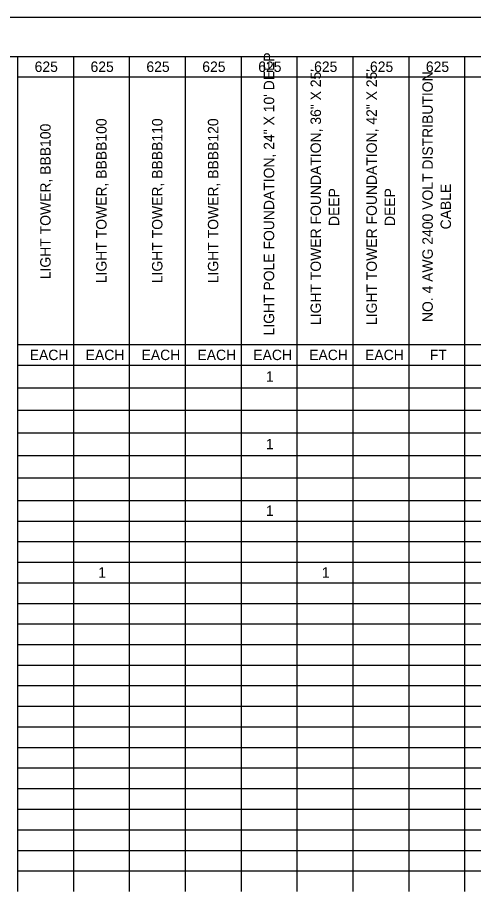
# Model space of a CAD drawing. Extents: x 0 to 34, y 0 to 22.
# Drawn here: x 12.63 to 18.49, y 10.78 to 22 of the extents above; entities that cross this region are included whole.
import ezdxf

# ---------------------------------------------------------------- set-up
doc = ezdxf.new("R2010")
doc.units = 0
for name, color, linetype in [('Default', 7, 'Continuous'), ('SH_Border', 7, 'Continuous'), ('SH_Cut_Line', 7, 'Continuous')]:
    doc.layers.add(name, color=color, linetype=linetype)

msp = doc.modelspace()

# ---------------------------------------------------------------- linework, layer by layer
at = {"layer": 'Default'}
for p, q in [((12.635, 21.5), (13.352, 21.5)), ((12.635, 21.5), (12.635, 21.236)), ((13.352, 21.5), (14.069, 21.5)), ((13.352, 21.5), (13.352, 21.236)), ((14.069, 21.5), (15.504, 21.5)), ((14.069, 21.5), (14.069, 21.236)), ((14.786, 21.5), (14.786, 21.236)), ((15.504, 21.5), (21.958, 21.5)), ((15.504, 21.5), (15.504, 21.236)), ((16.221, 21.5), (16.221, 21.236)), ((16.938, 21.5), (16.938, 21.236)), ((17.655, 21.5), (17.655, 21.236)), ((18.372, 21.5), (18.372, 21.236)), ((12.635, 21.236), (13.352, 21.236)), ((12.635, 21.236), (12.635, 20.972)), ((13.352, 21.236), (14.069, 21.236)), ((13.352, 21.236), (13.352, 20.972)), ((14.069, 21.236), (15.504, 21.236)), ((14.069, 21.236), (14.069, 20.972)), ((14.786, 21.236), (14.786, 20.972)), ((15.504, 21.236), (21.958, 21.236)), ((15.504, 21.236), (15.504, 20.972)), ((16.221, 21.236), (16.221, 20.972)), ((16.938, 21.236), (16.938, 20.972)), ((17.655, 21.236), (17.655, 20.972)), ((18.372, 21.236), (18.372, 20.972)), ((12.635, 20.972), (12.635, 20.707)), ((13.352, 20.972), (13.352, 20.707)), ((14.069, 20.972), (14.069, 20.707)), ((14.786, 20.972), (14.786, 20.707)), ((15.504, 20.972), (15.504, 20.707)), ((16.221, 20.972), (16.221, 20.707)), ((16.938, 20.972), (16.938, 20.707)), ((17.655, 20.972), (17.655, 20.707)), ((18.372, 20.972), (18.372, 20.707)), ((12.635, 20.707), (12.635, 20.443)), ((13.352, 20.707), (13.352, 20.443)), ((14.069, 20.707), (14.069, 20.443)), ((14.786, 20.707), (14.786, 20.443)), ((15.504, 20.707), (15.504, 20.443)), ((16.221, 20.707), (16.221, 20.443)), ((16.938, 20.707), (16.938, 20.443)), ((17.655, 20.707), (17.655, 20.443)), ((18.372, 20.707), (18.372, 20.443)), ((12.635, 20.443), (12.635, 20.179)), ((13.352, 20.443), (13.352, 20.179)), ((14.069, 20.443), (14.069, 20.179)), ((14.786, 20.443), (14.786, 20.179)), ((15.504, 20.443), (15.504, 20.179)), ((16.221, 20.443), (16.221, 20.179)), ((16.938, 20.443), (16.938, 20.179)), ((17.655, 20.443), (17.655, 20.179)), ((18.372, 20.443), (18.372, 20.179)), ((12.635, 20.179), (12.635, 19.915)), ((13.352, 20.179), (13.352, 19.915)), ((14.069, 20.179), (14.069, 19.915)), ((14.786, 20.179), (14.786, 19.915)), ((15.504, 20.179), (15.504, 19.915)), ((16.221, 20.179), (16.221, 19.915)), ((16.938, 20.179), (16.938, 19.915)), ((17.655, 20.179), (17.655, 19.915)), ((18.372, 20.179), (18.372, 19.915)), ((12.635, 19.915), (12.635, 19.651)), ((13.352, 19.915), (13.352, 19.651)), ((14.069, 19.915), (14.069, 19.651)), ((14.786, 19.915), (14.786, 19.651)), ((15.504, 19.915), (15.504, 19.651)), ((16.221, 19.915), (16.221, 19.651)), ((16.938, 19.915), (16.938, 19.651)), ((17.655, 19.915), (17.655, 19.651)), ((18.372, 19.915), (18.372, 19.651)), ((12.635, 19.651), (12.635, 19.122)), ((13.352, 19.651), (13.352, 19.122)), ((14.069, 19.651), (14.069, 19.122)), ((14.786, 19.651), (14.786, 19.122)), ((15.504, 19.651), (15.504, 19.122)), ((16.221, 19.651), (16.221, 19.122)), ((16.938, 19.651), (16.938, 19.122)), ((17.655, 19.651), (17.655, 19.122)), ((18.372, 19.651), (18.372, 19.122)), ((12.635, 19.122), (12.635, 18.329)), ((13.352, 19.122), (13.352, 18.329)), ((14.069, 19.122), (14.069, 18.329)), ((14.786, 19.122), (14.786, 18.329)), ((15.504, 19.122), (15.504, 18.329)), ((16.221, 19.122), (16.221, 18.329)), ((16.938, 19.122), (16.938, 18.329)), ((17.655, 19.122), (17.655, 18.329)), ((18.372, 19.122), (18.372, 18.329)), ((12.635, 18.329), (12.635, 18.065)), ((13.352, 18.329), (13.352, 18.065)), ((14.069, 18.329), (14.069, 18.065)), ((14.786, 18.329), (14.786, 18.065)), ((15.504, 18.329), (15.504, 18.065)), ((16.221, 18.329), (16.221, 18.065)), ((16.938, 18.329), (16.938, 18.065)), ((17.655, 18.329), (17.655, 18.065)), ((18.372, 18.329), (18.372, 18.065)), ((12.635, 18.065), (12.635, 17.537)), ((13.352, 18.065), (13.352, 17.537)), ((14.069, 18.065), (14.069, 17.537)), ((14.786, 18.065), (14.786, 17.537)), ((15.504, 18.065), (15.504, 17.537)), ((16.221, 18.065), (16.221, 17.537)), ((16.938, 18.065), (16.938, 17.537)), ((17.655, 18.065), (17.655, 17.537)), ((18.372, 18.065), (18.372, 17.537)), ((12.635, 17.801), (13.352, 17.801)), ((13.352, 17.801), (14.069, 17.801)), ((14.069, 17.801), (15.504, 17.801)), ((15.504, 17.801), (21.958, 17.801)), ((12.635, 17.537), (13.352, 17.537)), ((12.635, 17.537), (12.635, 17.247)), ((13.352, 17.537), (14.069, 17.537)), ((13.352, 17.537), (13.352, 17.247)), ((14.069, 17.537), (15.504, 17.537)), ((14.069, 17.537), (14.069, 17.247)), ((14.786, 17.537), (14.786, 17.247)), ((15.504, 17.537), (21.958, 17.537)), ((15.504, 17.537), (15.504, 17.247)), ((16.221, 17.537), (16.221, 17.247)), ((16.938, 17.537), (16.938, 17.247)), ((17.655, 17.537), (17.655, 17.247)), ((18.372, 17.537), (18.372, 17.247)), ((12.635, 17.247), (13.352, 17.247)), ((12.635, 17.247), (12.635, 15.801)), ((13.352, 17.247), (14.069, 17.247)), ((13.352, 17.247), (13.352, 15.801)), ((14.069, 17.247), (15.504, 17.247)), ((14.069, 17.247), (14.069, 15.801)), ((14.786, 17.247), (14.786, 15.801)), ((15.504, 17.247), (21.958, 17.247)), ((15.504, 17.247), (15.504, 15.801)), ((16.221, 17.247), (16.221, 15.801)), ((16.938, 17.247), (16.938, 15.801)), ((17.655, 17.247), (17.655, 15.801)), ((18.372, 17.247), (18.372, 15.801)), ((12.635, 16.958), (13.352, 16.958)), ((13.352, 16.958), (14.069, 16.958)), ((14.069, 16.958), (15.504, 16.958)), ((15.504, 16.958), (21.958, 16.958)), ((12.635, 16.669), (13.352, 16.669)), ((13.352, 16.669), (14.069, 16.669)), ((14.069, 16.669), (15.504, 16.669)), ((15.504, 16.669), (21.958, 16.669)), ((12.635, 16.379), (13.352, 16.379)), ((13.352, 16.379), (14.069, 16.379)), ((14.069, 16.379), (15.504, 16.379)), ((15.504, 16.379), (21.958, 16.379)), ((12.635, 16.09), (13.352, 16.09)), ((13.352, 16.09), (14.069, 16.09)), ((14.069, 16.09), (15.504, 16.09)), ((15.504, 16.09), (21.958, 16.09)), ((12.635, 15.801), (13.352, 15.801)), ((12.635, 15.801), (12.635, 15.272)), ((13.352, 15.801), (14.069, 15.801)), ((13.352, 15.801), (13.352, 15.272)), ((14.069, 15.801), (15.504, 15.801)), ((14.069, 15.801), (14.069, 15.272)), ((14.786, 15.801), (14.786, 15.272)), ((15.504, 15.801), (21.958, 15.801)), ((15.504, 15.801), (15.504, 15.272)), ((16.221, 15.801), (16.221, 15.272)), ((16.938, 15.801), (16.938, 15.272)), ((17.655, 15.801), (17.655, 15.272)), ((18.372, 15.801), (18.372, 15.272)), ((12.635, 15.536), (13.352, 15.536)), ((13.352, 15.536), (14.069, 15.536)), ((14.069, 15.536), (15.504, 15.536)), ((15.504, 15.536), (21.958, 15.536)), ((12.635, 15.272), (13.352, 15.272)), ((12.635, 15.272), (12.635, 15.008)), ((13.352, 15.272), (14.069, 15.272)), ((13.352, 15.272), (13.352, 15.008)), ((14.069, 15.272), (15.504, 15.272)), ((14.069, 15.272), (14.069, 15.008)), ((14.786, 15.272), (14.786, 15.008)), ((15.504, 15.272), (21.958, 15.272)), ((15.504, 15.272), (15.504, 15.008)), ((16.221, 15.272), (16.221, 15.008)), ((16.938, 15.272), (16.938, 15.008)), ((17.655, 15.272), (17.655, 15.008)), ((18.372, 15.272), (18.372, 15.008)), ((12.635, 15.008), (13.352, 15.008)), ((12.635, 15.008), (12.635, 14.479)), ((13.352, 15.008), (14.069, 15.008)), ((13.352, 15.008), (13.352, 14.479)), ((14.069, 15.008), (15.504, 15.008)), ((14.069, 15.008), (14.069, 14.479)), ((14.786, 15.008), (14.786, 14.479)), ((15.504, 15.008), (21.958, 15.008)), ((15.504, 15.008), (15.504, 14.479)), ((16.221, 15.008), (16.221, 14.479)), ((16.938, 15.008), (16.938, 14.479)), ((17.655, 15.008), (17.655, 14.479)), ((18.372, 15.008), (18.372, 14.479)), ((12.635, 14.744), (13.352, 14.744)), ((13.352, 14.744), (14.069, 14.744)), ((14.069, 14.744), (15.504, 14.744)), ((15.504, 14.744), (21.958, 14.744)), ((12.635, 14.479), (13.352, 14.479)), ((12.635, 14.479), (12.635, 13.423)), ((13.352, 14.479), (14.069, 14.479)), ((13.352, 14.479), (13.352, 13.423)), ((14.069, 14.479), (15.504, 14.479)), ((14.069, 14.479), (14.069, 13.423)), ((14.786, 14.479), (14.786, 13.423)), ((15.504, 14.479), (21.958, 14.479)), ((15.504, 14.479), (15.504, 13.423)), ((16.221, 14.479), (16.221, 13.423)), ((16.938, 14.479), (16.938, 13.423)), ((17.655, 14.479), (17.655, 13.423)), ((18.372, 14.479), (18.372, 13.423)), ((12.635, 14.215), (13.352, 14.215)), ((13.352, 14.215), (14.069, 14.215)), ((14.069, 14.215), (15.504, 14.215)), ((15.504, 14.215), (21.958, 14.215)), ((12.635, 13.951), (13.352, 13.951)), ((13.352, 13.951), (14.069, 13.951)), ((14.069, 13.951), (15.504, 13.951)), ((15.504, 13.951), (21.958, 13.951)), ((12.635, 13.687), (13.352, 13.687)), ((13.352, 13.687), (14.069, 13.687)), ((14.069, 13.687), (15.504, 13.687)), ((15.504, 13.687), (21.958, 13.687)), ((12.635, 13.423), (13.352, 13.423)), ((12.635, 13.423), (12.635, 13.158)), ((13.352, 13.423), (14.069, 13.423)), ((13.352, 13.423), (13.352, 13.158)), ((14.069, 13.423), (15.504, 13.423)), ((14.069, 13.423), (14.069, 13.158)), ((14.786, 13.423), (14.786, 13.158)), ((15.504, 13.423), (21.958, 13.423)), ((15.504, 13.423), (15.504, 13.158)), ((16.221, 13.423), (16.221, 13.158)), ((16.938, 13.423), (16.938, 13.158)), ((17.655, 13.423), (17.655, 13.158)), ((18.372, 13.423), (18.372, 13.158)), ((12.635, 13.158), (13.352, 13.158)), ((12.635, 13.158), (12.635, 12.894)), ((13.352, 13.158), (14.069, 13.158)), ((13.352, 13.158), (13.352, 12.894)), ((14.069, 13.158), (15.504, 13.158)), ((14.069, 13.158), (14.069, 12.894)), ((14.786, 13.158), (14.786, 12.894)), ((15.504, 13.158), (21.958, 13.158)), ((15.504, 13.158), (15.504, 12.894)), ((16.221, 13.158), (16.221, 12.894)), ((16.938, 13.158), (16.938, 12.894)), ((17.655, 13.158), (17.655, 12.894)), ((18.372, 13.158), (18.372, 12.894)), ((12.635, 12.894), (13.352, 12.894)), ((12.635, 12.894), (12.635, 12.101)), ((13.352, 12.894), (14.069, 12.894)), ((13.352, 12.894), (13.352, 12.101)), ((14.069, 12.894), (15.504, 12.894)), ((14.069, 12.894), (14.069, 12.101)), ((14.786, 12.894), (14.786, 12.101)), ((15.504, 12.894), (21.958, 12.894)), ((15.504, 12.894), (15.504, 12.101)), ((16.221, 12.894), (16.221, 12.101)), ((16.938, 12.894), (16.938, 12.101)), ((17.655, 12.894), (17.655, 12.101)), ((18.372, 12.894), (18.372, 12.101)), ((12.635, 12.63), (13.352, 12.63)), ((13.352, 12.63), (14.069, 12.63)), ((14.069, 12.63), (15.504, 12.63)), ((15.504, 12.63), (21.958, 12.63)), ((12.635, 12.366), (13.352, 12.366)), ((13.352, 12.366), (14.069, 12.366)), ((14.069, 12.366), (15.504, 12.366)), ((15.504, 12.366), (21.958, 12.366)), ((12.635, 12.101), (13.352, 12.101)), ((12.635, 12.101), (12.635, 11.573)), ((13.352, 12.101), (14.069, 12.101)), ((13.352, 12.101), (13.352, 11.573)), ((14.069, 12.101), (15.504, 12.101)), ((14.069, 12.101), (14.069, 11.573)), ((14.786, 12.101), (14.786, 11.573)), ((15.504, 12.101), (21.958, 12.101)), ((15.504, 12.101), (15.504, 11.573)), ((16.221, 12.101), (16.221, 11.573)), ((16.938, 12.101), (16.938, 11.573)), ((17.655, 12.101), (17.655, 11.573)), ((18.372, 12.101), (18.372, 11.573)), ((12.635, 11.837), (13.352, 11.837)), ((13.352, 11.837), (14.069, 11.837)), ((14.069, 11.837), (15.504, 11.837)), ((15.504, 11.837), (21.958, 11.837)), ((12.635, 11.573), (13.352, 11.573)), ((12.635, 11.573), (12.635, 10.78)), ((13.352, 11.573), (14.069, 11.573)), ((13.352, 11.573), (13.352, 10.78)), ((14.069, 11.573), (15.504, 11.573)), ((14.069, 11.573), (14.069, 10.78)), ((14.786, 11.573), (14.786, 10.78)), ((15.504, 11.573), (21.958, 11.573)), ((15.504, 11.573), (15.504, 10.78)), ((16.221, 11.573), (16.221, 10.78)), ((16.938, 11.573), (16.938, 10.78)), ((17.655, 11.573), (17.655, 10.78)), ((18.372, 11.573), (18.372, 10.78)), ((12.635, 11.309), (13.352, 11.309)), ((13.352, 11.309), (14.069, 11.309)), ((14.069, 11.309), (15.504, 11.309)), ((15.504, 11.309), (21.958, 11.309)), ((12.635, 11.045), (13.352, 11.045)), ((13.352, 11.045), (14.069, 11.045)), ((14.069, 11.045), (15.504, 11.045)), ((15.504, 11.045), (21.958, 11.045))]:
    msp.add_line(p, q, dxfattribs=at)
at = {"layer": 'SH_Border'}
msp.add_lwpolyline([(1.5, 21.5), (33.5, 21.5), (33.5, 0.5), (1.5, 0.5)], close=True, dxfattribs=at)
at = {"layer": 'SH_Cut_Line'}
msp.add_lwpolyline([(0, 0), (34, 0), (34, 22), (0, 22)], close=True, dxfattribs=at)

# ---------------------------------------------------------------- texts
at = {"layer": 'Default'}
for s, height, p in [('LIGHT POLE FOUNDATION, 24" X 10\' DEEP', 0.13368, (15.929, 17.918)), ('LIGHT TOWER FOUNDATION, 36" X 25\' ', 0.13368, (16.529, 18.052)), ('LIGHT TOWER FOUNDATION, 42" X 25\' ', 0.13368, (17.246, 18.052)), ('NO. 4 AWG 2400 VOLT DISTRIBUTION ', 0.13368, (17.964, 18.09)), ('LIGHT TOWER, BBBB100', 0.13368, (13.778, 18.589)), ('LIGHT TOWER, BBBB110', 0.13368, (14.495, 18.589)), ('LIGHT TOWER, BBBB120', 0.13368, (15.212, 18.589)), ('LIGHT TOWER, BBB100', 0.13368, (13.06, 18.64)), ('CABLE', 0.1337, (18.197, 19.28)), ('DEEP', 0.1337, (16.763, 19.323)), ('DEEP', 0.1337, (17.48, 19.323))]:
    msp.add_text(s, height=height, rotation=90, dxfattribs=at).set_placement(p)
for s, height, p in [('625', 0.1337, (12.855, 21.301)), ('625', 0.1337, (13.572, 21.301)), ('625', 0.1337, (14.289, 21.301)), ('625', 0.1337, (15.006, 21.301)), ('625', 0.1337, (15.724, 21.301)), ('625', 0.1337, (16.441, 21.301)), ('625', 0.1337, (17.158, 21.301)), ('625', 0.1337, (17.875, 21.301)), ('EACH', 0.1337, (12.792, 17.602)), ('EACH', 0.1337, (13.51, 17.602)), ('EACH', 0.1337, (14.227, 17.602)), ('EACH', 0.1337, (14.944, 17.602)), ('EACH', 0.1337, (15.661, 17.602)), ('EACH', 0.1337, (16.378, 17.602)), ('EACH', 0.1337, (17.095, 17.602)), ('FT', 0.1337, (17.925, 17.602)), ('1', 0.134, (15.823, 17.325)), ('1', 0.134, (15.823, 16.457)), ('1', 0.134, (15.823, 15.602)), ('1', 0.134, (13.671, 14.809)), ('1', 0.134, (16.54, 14.809))]:
    msp.add_text(s, height=height, dxfattribs=at).set_placement(p)

doc.saveas('drawing.dxf')
